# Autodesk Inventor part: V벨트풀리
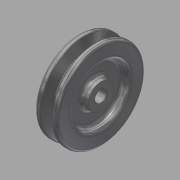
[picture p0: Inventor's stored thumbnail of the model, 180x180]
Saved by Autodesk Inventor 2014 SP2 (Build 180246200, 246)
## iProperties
Created: 2015-11
Part Number: V벨트풀리
Material: 강철, 탄소
Document SubType Name: Modeling
Designer: mduedu
Density: 1 g/cm^3
Appearance: 반광택
Author: mduedu
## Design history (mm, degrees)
sketch "스케치1"
  geometry: L1 (-9.5, 0)-(9.5, 0); L2 (0, 0)-(0, 37.7); L3 (-4.825, 37.7)-(-9.5, 37.7); L4 (-9.5, 37.7)-(-9.5, 0); L5 (0, 28.7)-(-2.074, 28.7); L6 (-2.074, 28.7)-(-4.825, 37.7); L7 (4.825, 37.7)-(9.5, 37.7); L8 (9.5, 37.7)-(9.5, 0); L9 (0, 28.7)-(2.074, 28.7); L10 (2.074, 28.7)-(4.825, 37.7); L11 (-9.5, 35)-(9.5, 35); 3 further points
  constraints: 22 end point, 7 point on line, 4 perpendicular, 3 symmetric about line, 1 coincident, 1 horizontal, 1 horizontal alignment, 1 midpoint, 1 vertical
  dimensions: "d0" = 19 distance of L1.start L1.end; "d2" = 75.4 diameter of L2.end L1 (derived); "d3" = 34 deg angle of L10 L6; "d4" = 6.3 distance between parallel lines of L11 L9; "d5" = 2.7 distance between parallel lines of L7 L11; "d6" = 8 distance of point (4, 35) point (-4, 35); "d7" = 70 diameter of L11 L1
revolve "회전1" sketch "스케치1" stored, may be unused: angle "d8" = 90 deg
sketch "스케치2"
  geometry: C1 r 24 at (0, 0); C2 r 11 at (0, 0); 1 further point
  constraints: 2 centre point, 2 coincident
  dimensions: "d9" = 48 diameter of C1; "d10" = 22 diameter of C2
extrude "돌출1" cut sketch "스케치2" distance "d11" = 6; taper "d12" = 0 deg
fillet "모깎기1" dims "d13" = 3
fillet "모깎기2" dims "d14" = 3
fillet "모깎기3" dims "d15" = 1, "d16" = 0.5, "d17" = 2
hole "구멍1" diameter "d20" = 10; stored, may be unused: countersink angle "d24" = 90 deg, drill point angle "d26" = 118 deg; dims "d18" = 10, "d19" = 10, "d21" = 6, "d22" = 4, "d23" = 2, "d25" = 8
sketch "스케치3"
  geometry: L1 (-1.5, 0)-(1.5, 0); L2 (1.5, 0)-(1.5, 6.4); L3 (1.5, 6.4)-(-1.5, 6.4); L4 (-1.5, 6.4)-(-1.5, 0); 2 further points
  constraints: 8 end point, 2 parallel, 1 coincident, 1 horizontal, 1 midpoint, 1 perpendicular
  dimensions: "d27" = 3 distance of L2.end L3.end; "d29" = 6.4 distance of L3.end L1.start
extrude "돌출2" cut sketch "스케치3" stored distance "d30" = 6; taper "d31" = 0 deg
chamfer "모따기1" distance "d32" = 0.5; stored, may be unused: second distance "d33" = 2, angle "d34" = 45 deg
node "솔리드1"
mirror "대칭1"
